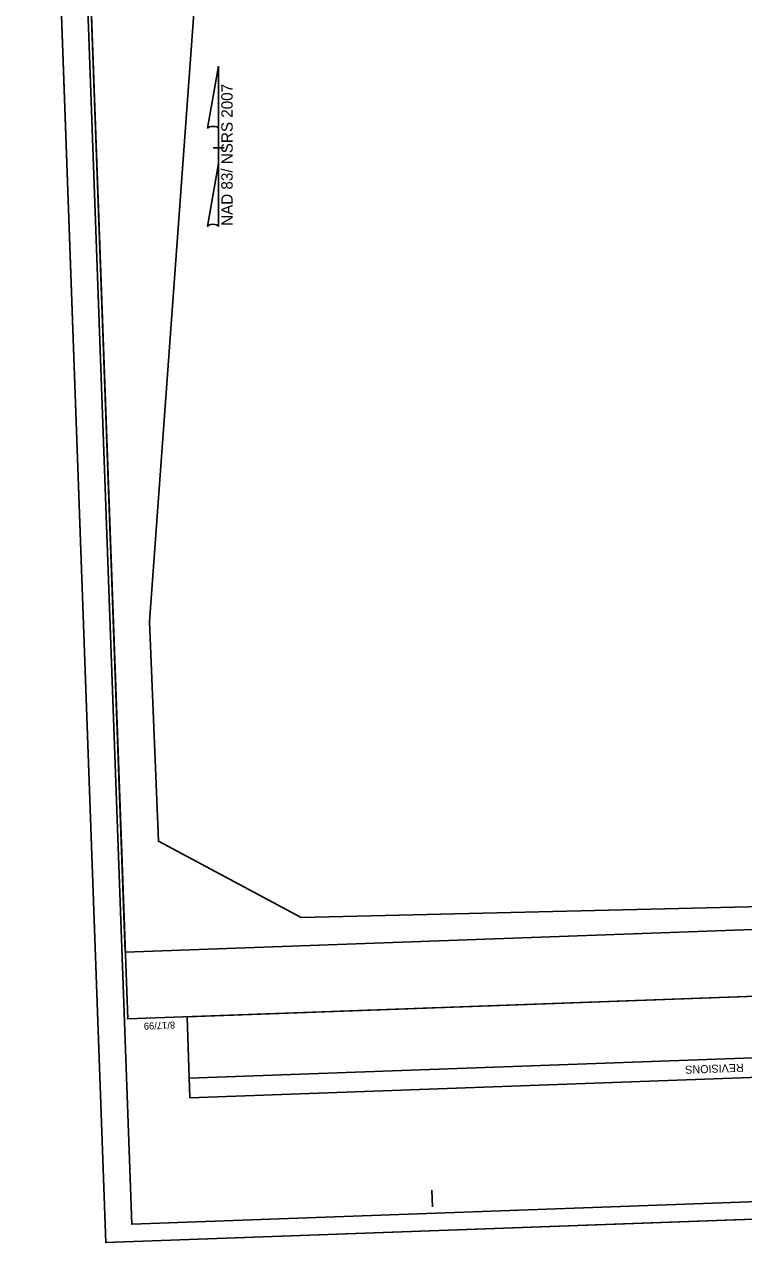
# Model space of a CAD drawing. Extents: x 2065068 to 2066582, y 144283 to 146300.
# Drawn here: x 2065427 to 2065965, y 144306 to 145217 of the extents above; entities that cross this region are included whole.
import ezdxf

# ---------------------------------------------------------------- set-up
doc = ezdxf.new("R2010")
doc.units = 0
for name, color, linetype in [('Prop North Arrow NAD83 for Plan Sheets CELL', 7, 'Continuous'), ('Sheet Block Revision CELL', 7, 'Continuous'), ('Sheet Clip Boundary CELL', 7, 'Continuous'), ('Sheet Cutting Line CELL', 7, 'Continuous'), ('Sheet Layout Plan Border', 7, 'Continuous'), ('Sheet Plan CELL', 7, 'Continuous'), ('Sheet Plan Layout CELL', 7, 'Continuous'), ('Sheet Plot Border Inside CELL', 7, 'Continuous'), ('Sheet Plot Border Outside CELL', 7, 'Continuous')]:
    doc.layers.add(name, color=color, linetype=linetype)

msp = doc.modelspace()

# ---------------------------------------------------------------- linework, layer by layer
at = {"layer": 'Prop North Arrow NAD83 for Plan Sheets CELL'}
for p, q in [((2065564.28, 145139.41), (2065572.48, 145185.76)), ((2065572.53, 145185.76), (2065572.48, 145185.76)), ((2065572.53, 145185.76), (2065572.48, 145185.76)), ((2065572.53, 145185.76), (2065572.53, 145137.96)), ((2065572.53, 145113.16), (2065572.53, 145139.36)), ((2065572.53, 145137.96), (2065572.53, 145139.31)), ((2065568.53, 145124.76), (2065568.48, 145124.76)), ((2065572.08, 145124.76), (2065568.53, 145124.76)), ((2065568.58, 145124.76), (2065576.58, 145124.76)), ((2065572.53, 145113.16), (2065564.18, 145065.91)), ((2065572.58, 145066.11), (2065572.53, 145113.16))]:
    msp.add_line(p, q, dxfattribs=at)
for centre, start_param, end_param in [((2065568.42, 145138.91), 0.216388, 2.908219), ((2065568.42, 145065.74), 0.201328, 3.141593)]:
    msp.add_ellipse(centre, major_axis=(4.23, -0.03), ratio=0.461098, start_param=start_param, end_param=end_param, dxfattribs=at)
at = {"layer": 'Sheet Block Revision CELL'}
msp.add_line((2066340.72, 144457.89), (2065550.59, 144429.32), dxfattribs=at)
msp.add_lwpolyline([(2066341.27, 144443.35), (2065551.13, 144414.79), (2065548.92, 144475.29), (2066339.05, 144503.85)], close=True, dxfattribs=at)
at = {"layer": 'Sheet Clip Boundary CELL'}
msp.add_lwpolyline([(2066209.26, 144563.12), (2066197.36, 145017.22), (2066304.56, 145076.85), (2066276.35, 145857.16), (2065667.01, 145835.13), (2065670.41, 145741.24), (2065591.32, 145738.38), (2065521, 144770.65), (2065527.51, 144606.5), (2065634.3, 144549.42)], close=True, dxfattribs=at)
at = {"layer": 'Sheet Cutting Line CELL'}
for p, q in [((2065427.33, 145988.88), (2065488.14, 144306.48)), ((2065488.14, 144306.48), (2066582.43, 144346.04))]:
    msp.add_line(p, q, dxfattribs=at)
at = {"layer": 'Sheet Layout Plan Border'}
msp.add_lwpolyline([(2066552.11, 144561.57), (2066501.53, 145960.67), (2065663.57, 145930.38), (2065670.41, 145741.24), (2065459.06, 145733.6), (2065502.79, 144523.64)], close=True, dxfattribs=at)
at = {"layer": 'Sheet Plan CELL'}
for p, q in [((2065504.6, 144473.67), (2065504.6, 144473.67)), ((2065732.34, 144333.31), (2065731.87, 144345.81))]:
    msp.add_line(p, q, dxfattribs=at)
for points in [[(2065450.41, 145972.73), (2065504.6, 144473.67), (2066553.91, 144511.61), (2066499.73, 146010.64)], [(2066553.91, 144511.61), (2065504.63, 144473.65), (2065457.63, 145772.79), (2065607.59, 145778.22), (2065600.38, 145978.13), (2066499.73, 146010.64)]]:
    msp.add_lwpolyline(points, close=True, dxfattribs=at)
at = {"layer": 'Sheet Plan Layout CELL'}
msp.add_lwpolyline([(2065504.63, 144473.65), (2066553.91, 144511.61), (2066499.73, 146010.63), (2065661.76, 145980.34), (2065670.41, 145741.24), (2065459.06, 145733.6)], close=True, dxfattribs=at)
at = {"layer": 'Sheet Plot Border Inside CELL'}
msp.add_lwpolyline([(2066561.97, 144358.31), (2066501.77, 146023.21), (2065447.47, 145985.11), (2065507.66, 144320.2)], close=True, dxfattribs=at)
at = {"layer": 'Sheet Plot Border Outside CELL'}
msp.add_lwpolyline([(2066582.43, 144346.04), (2066521.61, 146028.44), (2065427.33, 145988.88), (2065488.14, 144306.48)], close=True, dxfattribs=at)

# ---------------------------------------------------------------- texts
at = {"layer": 'Prop North Arrow NAD83 for Plan Sheets CELL'}
msp.add_text('NAD 83/ NSRS 2007', height=8.5, rotation=90, dxfattribs=at).set_placement((2065583.05, 145066.46))
at = {"layer": 'Sheet Block Revision CELL'}
msp.add_text('REVISIONS', height=6, rotation=182.07024, dxfattribs=at).set_placement((2065964.96, 144440.26))
at = {"layer": 'Sheet Plan CELL'}
msp.add_text('8/17/99', height=5.25, rotation=182.07025, dxfattribs=at).set_placement((2065539.92, 144471.72))

doc.saveas('drawing.dxf')
